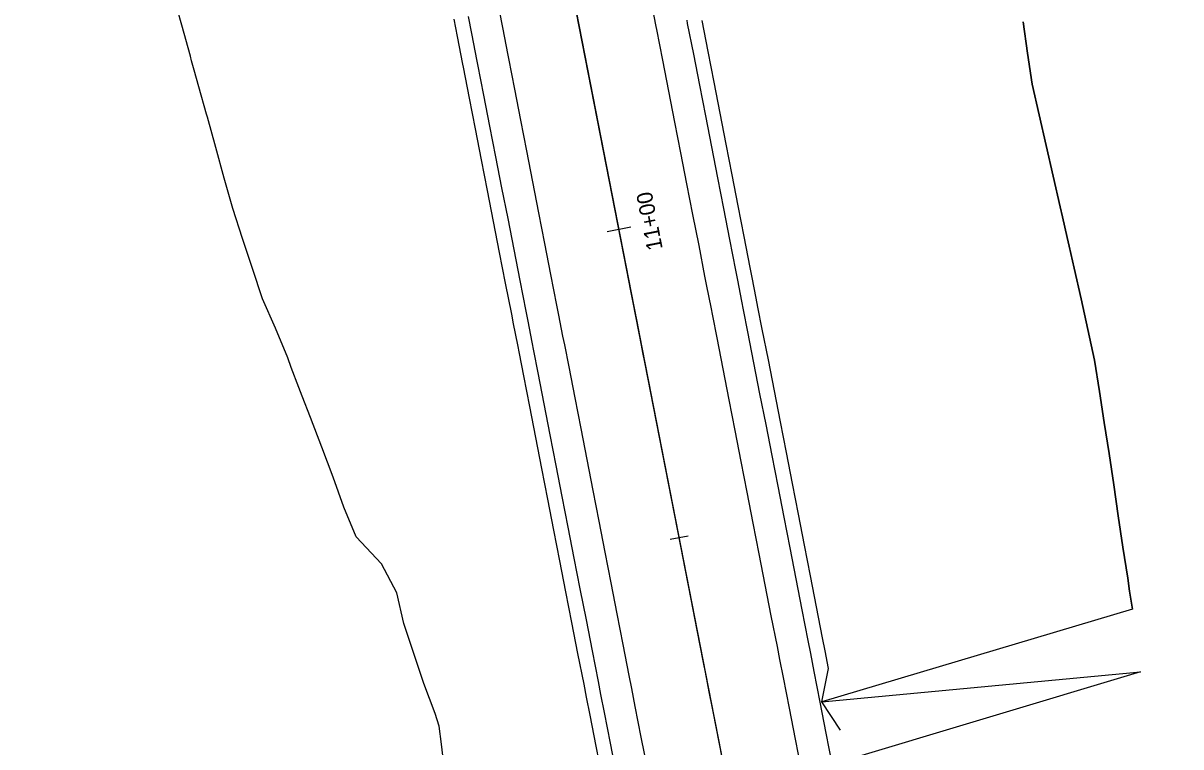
# Model space of a CAD drawing. Extents: x 1150550 to 1151113, y 1141187 to 1143500.
# Drawn here: x 1150688.9 to 1150873.1, y 1142001 to 1142116.1 of the extents above; entities that cross this region are included whole.
import ezdxf

# ---------------------------------------------------------------- set-up
doc = ezdxf.new("R2010")
doc.units = 0
for name, color, linetype in [('AC_P', 7, 'Continuous'), ('ACSR_P_T', 7, 'Continuous'), ('ACSRT_P', 7, 'Continuous'), ('Default', 7, 'Continuous'), ('LELB_P', 7, 'Continuous'), ('LFILL_P', 7, 'Continuous'), ('PE_P', 7, 'Continuous'), ('PET_P', 7, 'Continuous'), ('XSCTOP1_P', 7, 'Continuous')]:
    doc.layers.add(name, color=color, linetype=linetype)

msp = doc.modelspace()

# ---------------------------------------------------------------- linework, layer by layer
at = {"layer": 'AC_P'}
msp.add_line((1150819.56, 1141899.84), (1150776.47, 1142120.43), dxfattribs=at)
msp.add_lwpolyline([(1150800.01, 1141999.94), (1150799.05, 1142004.85), (1150798.09, 1142009.76), (1150797.53, 1142012.61), (1150797.13, 1142014.67), (1150796.17, 1142019.57), (1150795.21, 1142024.48), (1150794.26, 1142029.39), (1150793.3, 1142034.3), (1150792.34, 1142039.2), (1150791.38, 1142044.11), (1150790.42, 1142049.02), (1150789.46, 1142053.92), (1150788.5, 1142058.83), (1150787.54, 1142063.74), (1150786.86, 1142067.26), (1150786.59, 1142068.65), (1150785.94, 1142071.98), (1150785.63, 1142073.55), (1150784.67, 1142078.46), (1150783.71, 1142083.37), (1150782.75, 1142088.27), (1150781.79, 1142093.18), (1150780.83, 1142098.09), (1150779.88, 1142103), (1150778.92, 1142107.9), (1150777.96, 1142112.81), (1150777.86, 1142113.3), (1150777, 1142117.72)], dxfattribs=at)
at = {"layer": 'ACSRT_P'}
for points in [[(1150781.83, 1142083), (1150785.59, 1142083.74)], [(1150791.88, 1142034.02), (1150794.71, 1142034.57)]]:
    msp.add_lwpolyline(points, dxfattribs=at)
at = {"layer": 'Default'}
msp.add_line((1150956.27, 1141200.06), (1150657.48, 1142729.55), dxfattribs=at)
at = {"layer": 'LELB_P'}
for points in [[(1150756.08, 1141996.46), (1150755.47, 1142001.43), (1150755.12, 1142004.32), (1150754.48, 1142006.33), (1150752.66, 1142011.07), (1150751.09, 1142015.86), (1150749.51, 1142020.65), (1150748.4, 1142025.52), (1150745.97, 1142030.14), (1150741.91, 1142034.44), (1150739.96, 1142039.16), (1150738.25, 1142043.92), (1150736.45, 1142048.66), (1150734.64, 1142053.4), (1150733.34, 1142056.8), (1150732.82, 1142058.14), (1150731.6, 1142061.36), (1150731.02, 1142062.88), (1150729.1, 1142067.6), (1150727, 1142072.29), (1150725.43, 1142077.08), (1150723.86, 1142081.86), (1150722.3, 1142086.65), (1150720.92, 1142091.48), (1150719.59, 1142096.31), (1150718.25, 1142101.15), (1150718.12, 1142101.63), (1150716.9, 1142105.98), (1150716.16, 1142108.65), (1150715.74, 1142110.14), (1150715.54, 1142110.86), (1150714.17, 1142115.8), (1150712.81, 1142120.74)], [(1150781.03, 1141996.24), (1150780.07, 1142001.14), (1150779.12, 1142006.05), (1150778.56, 1142008.9), (1150778.16, 1142010.96), (1150777.2, 1142015.87), (1150776.24, 1142020.77), (1150775.28, 1142025.68), (1150774.32, 1142030.59), (1150773.36, 1142035.5), (1150772.4, 1142040.4), (1150771.45, 1142045.31), (1150770.49, 1142050.22), (1150769.53, 1142055.12), (1150768.57, 1142060.03), (1150767.88, 1142063.55), (1150767.61, 1142064.94), (1150766.96, 1142068.27), (1150766.65, 1142069.85), (1150765.69, 1142074.75), (1150764.74, 1142079.66), (1150763.78, 1142084.57), (1150762.82, 1142089.48), (1150761.86, 1142094.38), (1150760.9, 1142099.29), (1150759.94, 1142104.2), (1150758.98, 1142109.1), (1150758.89, 1142109.59), (1150758.02, 1142114.01), (1150757.5, 1142116.72)], [(1150818.98, 1142003.65), (1150815.98, 1142008.16), (1150817.06, 1142013.47), (1150816.51, 1142016.31), (1150816.11, 1142018.37), (1150815.15, 1142023.28), (1150814.19, 1142028.19), (1150813.23, 1142033.09), (1150812.27, 1142038), (1150811.31, 1142042.91), (1150810.35, 1142047.82), (1150809.4, 1142052.72), (1150808.44, 1142057.63), (1150807.48, 1142062.54), (1150806.52, 1142067.45), (1150805.83, 1142070.96), (1150805.56, 1142072.35), (1150804.91, 1142075.68), (1150804.6, 1142077.26), (1150803.64, 1142082.17), (1150802.68, 1142087.07), (1150801.73, 1142091.98), (1150800.77, 1142096.89), (1150799.81, 1142101.8), (1150798.85, 1142106.7), (1150797.89, 1142111.61), (1150796.93, 1142116.52)], [(1150848.01, 1142116.31), (1150848.69, 1142111.35), (1150849.44, 1142106.4), (1150850.56, 1142101.52), (1150851.67, 1142096.64), (1150852.79, 1142091.77), (1150853.9, 1142086.89), (1150854.26, 1142085.32), (1150855.01, 1142082.01), (1150855.33, 1142080.63), (1150856.12, 1142077.14), (1150857.22, 1142072.26), (1150858.31, 1142067.37), (1150859.37, 1142062.49), (1150860.17, 1142057.55), (1150860.92, 1142052.6), (1150861.67, 1142047.65), (1150862.41, 1142042.7), (1150863.14, 1142037.75), (1150863.89, 1142032.8), (1150864.64, 1142027.85), (1150864.95, 1142025.78), (1150865.39, 1142022.91), (1150815.98, 1142008.16), (1150866.65, 1142012.96), (1150818.1, 1141998.38)]]:
    msp.add_lwpolyline(points, dxfattribs=at)
at = {"layer": 'LFILL_P'}
for points in [[(1150756.08, 1141996.46), (1150755.47, 1142001.43), (1150755.12, 1142004.32), (1150754.48, 1142006.33), (1150752.66, 1142011.07), (1150751.09, 1142015.86), (1150749.51, 1142020.65), (1150748.4, 1142025.52), (1150745.97, 1142030.14), (1150741.91, 1142034.44), (1150739.96, 1142039.16), (1150738.25, 1142043.92), (1150736.45, 1142048.66), (1150734.64, 1142053.4), (1150733.34, 1142056.8), (1150732.82, 1142058.14), (1150731.6, 1142061.36), (1150731.02, 1142062.88), (1150729.1, 1142067.6), (1150727, 1142072.29), (1150725.43, 1142077.08), (1150723.86, 1142081.86), (1150722.3, 1142086.65), (1150720.92, 1142091.48), (1150719.59, 1142096.31), (1150718.25, 1142101.15), (1150718.12, 1142101.63), (1150716.9, 1142105.98), (1150716.16, 1142108.65), (1150715.74, 1142110.14), (1150715.54, 1142110.86), (1150714.17, 1142115.8), (1150712.81, 1142120.74)], [(1150865.39, 1142022.91), (1150864.95, 1142025.78), (1150864.64, 1142027.85), (1150863.89, 1142032.8), (1150863.14, 1142037.75), (1150862.41, 1142042.7), (1150861.67, 1142047.65), (1150860.92, 1142052.6), (1150860.17, 1142057.55), (1150859.37, 1142062.49), (1150858.31, 1142067.37), (1150857.22, 1142072.26), (1150856.12, 1142077.14), (1150855.33, 1142080.63), (1150855.01, 1142082.01), (1150854.26, 1142085.32), (1150853.9, 1142086.89), (1150852.79, 1142091.77), (1150851.67, 1142096.64), (1150850.56, 1142101.52), (1150849.44, 1142106.4), (1150848.69, 1142111.35), (1150848.01, 1142116.31)]]:
    msp.add_lwpolyline(points, dxfattribs=at)
at = {"layer": 'PE_P'}
for points in [[(1150783.32, 1141996.68), (1150782.36, 1142001.59), (1150781.41, 1142006.5), (1150780.85, 1142009.35), (1150780.45, 1142011.41), (1150779.49, 1142016.31), (1150778.53, 1142021.22), (1150777.57, 1142026.13), (1150776.61, 1142031.04), (1150775.65, 1142035.94), (1150774.69, 1142040.85), (1150773.74, 1142045.76), (1150772.78, 1142050.66), (1150771.82, 1142055.57), (1150770.86, 1142060.48), (1150770.17, 1142064), (1150769.9, 1142065.39), (1150769.25, 1142068.72), (1150768.94, 1142070.29), (1150767.98, 1142075.2), (1150767.03, 1142080.11), (1150766.07, 1142085.02), (1150765.11, 1142089.92), (1150764.15, 1142094.83), (1150763.19, 1142099.74), (1150762.23, 1142104.64), (1150761.27, 1142109.55), (1150761.18, 1142110.04), (1150760.31, 1142114.46), (1150759.79, 1142117.17)], [(1150817.65, 1141998.3), (1150816.69, 1142003.2), (1150815.73, 1142008.11), (1150814.77, 1142013.02), (1150814.22, 1142015.86), (1150813.82, 1142017.93), (1150812.86, 1142022.83), (1150811.9, 1142027.74), (1150810.94, 1142032.65), (1150809.98, 1142037.55), (1150809.02, 1142042.46), (1150808.06, 1142047.37), (1150807.11, 1142052.28), (1150806.15, 1142057.18), (1150805.19, 1142062.09), (1150804.23, 1142067), (1150803.54, 1142070.52), (1150803.27, 1142071.91), (1150802.62, 1142075.23), (1150802.31, 1142076.81), (1150801.35, 1142081.72), (1150800.39, 1142086.63), (1150799.44, 1142091.53), (1150798.48, 1142096.44), (1150797.52, 1142101.35), (1150796.56, 1142106.26), (1150795.6, 1142111.16), (1150794.64, 1142116.07), (1150794.55, 1142116.56)]]:
    msp.add_lwpolyline(points, dxfattribs=at)
at = {"layer": 'PET_P'}
for points in [[(1150812.74, 1141997.34), (1150811.78, 1142002.25), (1150810.83, 1142007.15), (1150809.87, 1142012.06), (1150809.31, 1142014.91), (1150808.91, 1142016.97), (1150807.95, 1142021.87), (1150806.99, 1142026.78), (1150806.03, 1142031.69), (1150805.07, 1142036.6), (1150804.12, 1142041.5), (1150803.16, 1142046.41), (1150802.2, 1142051.32), (1150801.24, 1142056.22), (1150800.28, 1142061.13), (1150799.32, 1142066.04), (1150798.63, 1142069.56), (1150798.36, 1142070.95), (1150797.71, 1142074.28), (1150797.4, 1142075.85), (1150796.45, 1142080.76), (1150795.49, 1142085.67), (1150794.53, 1142090.58), (1150793.57, 1142095.48), (1150792.61, 1142100.39), (1150791.65, 1142105.3), (1150790.69, 1142110.2), (1150789.74, 1142115.11), (1150789.64, 1142115.6), (1150788.78, 1142120.02)], [(1150788.23, 1141997.64), (1150787.27, 1142002.55), (1150786.31, 1142007.46), (1150785.76, 1142010.3), (1150785.35, 1142012.37), (1150784.4, 1142017.27), (1150783.44, 1142022.18), (1150782.48, 1142027.09), (1150781.52, 1142031.99), (1150780.56, 1142036.9), (1150779.6, 1142041.81), (1150778.64, 1142046.72), (1150777.68, 1142051.62), (1150776.73, 1142056.53), (1150775.77, 1142061.44), (1150775.08, 1142064.96), (1150774.81, 1142066.34), (1150774.16, 1142069.67), (1150773.85, 1142071.25), (1150772.89, 1142076.16), (1150771.93, 1142081.07), (1150770.97, 1142085.97), (1150770.02, 1142090.88), (1150769.06, 1142095.79), (1150768.1, 1142100.7), (1150767.14, 1142105.6), (1150766.18, 1142110.51), (1150766.08, 1142111), (1150765.22, 1142115.42), (1150764.69, 1142118.13)]]:
    msp.add_lwpolyline(points, dxfattribs=at)
at = {"layer": 'XSCTOP1_P'}
for points in [[(1150812.74, 1141997.34), (1150811.78, 1142002.25), (1150810.83, 1142007.15), (1150809.87, 1142012.06), (1150809.31, 1142014.91), (1150808.91, 1142016.97), (1150807.95, 1142021.87), (1150806.99, 1142026.78), (1150806.03, 1142031.69), (1150805.07, 1142036.6), (1150804.12, 1142041.5), (1150803.16, 1142046.41), (1150802.2, 1142051.32), (1150801.24, 1142056.22), (1150800.28, 1142061.13), (1150799.32, 1142066.04), (1150798.63, 1142069.56), (1150798.36, 1142070.95), (1150797.71, 1142074.28), (1150797.4, 1142075.85), (1150796.45, 1142080.76), (1150795.49, 1142085.67), (1150794.53, 1142090.58), (1150793.57, 1142095.48), (1150792.61, 1142100.39), (1150791.65, 1142105.3), (1150790.69, 1142110.2), (1150789.74, 1142115.11), (1150789.64, 1142115.6), (1150788.78, 1142120.02)], [(1150783.32, 1141996.68), (1150782.36, 1142001.59), (1150781.41, 1142006.5), (1150780.85, 1142009.35), (1150780.45, 1142011.41), (1150779.49, 1142016.31), (1150778.53, 1142021.22), (1150777.57, 1142026.13), (1150776.61, 1142031.04), (1150775.65, 1142035.94), (1150774.69, 1142040.85), (1150773.74, 1142045.76), (1150772.78, 1142050.66), (1150771.82, 1142055.57), (1150770.86, 1142060.48), (1150770.17, 1142064), (1150769.9, 1142065.39), (1150769.25, 1142068.72), (1150768.94, 1142070.29), (1150767.98, 1142075.2), (1150767.03, 1142080.11), (1150766.07, 1142085.02), (1150765.11, 1142089.92), (1150764.15, 1142094.83), (1150763.19, 1142099.74), (1150762.23, 1142104.64), (1150761.27, 1142109.55), (1150761.18, 1142110.04), (1150760.31, 1142114.46), (1150759.79, 1142117.17)], [(1150788.23, 1141997.64), (1150787.27, 1142002.55), (1150786.31, 1142007.46), (1150785.76, 1142010.3), (1150785.35, 1142012.37), (1150784.4, 1142017.27), (1150783.44, 1142022.18), (1150782.48, 1142027.09), (1150781.52, 1142031.99), (1150780.56, 1142036.9), (1150779.6, 1142041.81), (1150778.64, 1142046.72), (1150777.68, 1142051.62), (1150776.73, 1142056.53), (1150775.77, 1142061.44), (1150775.08, 1142064.96), (1150774.81, 1142066.34), (1150774.16, 1142069.67), (1150773.85, 1142071.25), (1150772.89, 1142076.16), (1150771.93, 1142081.07), (1150770.97, 1142085.97), (1150770.02, 1142090.88), (1150769.06, 1142095.79), (1150768.1, 1142100.7), (1150767.14, 1142105.6), (1150766.18, 1142110.51), (1150766.08, 1142111), (1150765.22, 1142115.42), (1150764.69, 1142118.13)], [(1150800.01, 1141999.94), (1150799.05, 1142004.85), (1150798.09, 1142009.76), (1150797.53, 1142012.61), (1150797.13, 1142014.67), (1150796.17, 1142019.57), (1150795.21, 1142024.48), (1150794.26, 1142029.39), (1150793.3, 1142034.3), (1150792.34, 1142039.2), (1150791.38, 1142044.11), (1150790.42, 1142049.02), (1150789.46, 1142053.92), (1150788.5, 1142058.83), (1150787.54, 1142063.74), (1150786.86, 1142067.26), (1150786.59, 1142068.65), (1150785.94, 1142071.98), (1150785.63, 1142073.55), (1150784.67, 1142078.46), (1150783.71, 1142083.37), (1150782.75, 1142088.27), (1150781.79, 1142093.18), (1150780.83, 1142098.09), (1150779.88, 1142103), (1150778.92, 1142107.9), (1150777.96, 1142112.81), (1150777.86, 1142113.3), (1150777, 1142117.72)], [(1150817.65, 1141998.3), (1150816.69, 1142003.2), (1150815.73, 1142008.11), (1150814.77, 1142013.02), (1150814.22, 1142015.86), (1150813.82, 1142017.93), (1150812.86, 1142022.83), (1150811.9, 1142027.74), (1150810.94, 1142032.65), (1150809.98, 1142037.55), (1150809.02, 1142042.46), (1150808.06, 1142047.37), (1150807.11, 1142052.28), (1150806.15, 1142057.18), (1150805.19, 1142062.09), (1150804.23, 1142067), (1150803.54, 1142070.52), (1150803.27, 1142071.91), (1150802.62, 1142075.23), (1150802.31, 1142076.81), (1150801.35, 1142081.72), (1150800.39, 1142086.63), (1150799.44, 1142091.53), (1150798.48, 1142096.44), (1150797.52, 1142101.35), (1150796.56, 1142106.26), (1150795.6, 1142111.16), (1150794.64, 1142116.07), (1150794.55, 1142116.56)]]:
    msp.add_lwpolyline(points, dxfattribs=at)

# ---------------------------------------------------------------- texts
at = {"layer": 'ACSR_P_T'}
msp.add_text('11+00', height=2.501, rotation=101.0539, dxfattribs=at).set_placement((1150790.69, 1142080.24))

doc.saveas('drawing.dxf')
